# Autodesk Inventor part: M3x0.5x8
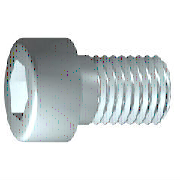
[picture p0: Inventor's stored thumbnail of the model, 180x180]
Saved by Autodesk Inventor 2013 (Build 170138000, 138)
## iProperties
IsCustomPart: 1
Company: 한국ATC센터
Created: 2009-02
Part Number: M3x0.5x8
Material: 강, 연강
Description: 6각머리 태핑 나사
Document SubType Name: Modeling
Standard: KS B 1003
Designer: KYOUNG IL JANG
Standards Organization: KS
Language: ko-KR
Size Designation: M 4 x 12
Categories: <MemberInstance><Categories><Category DisplayName="조임쇠" InternalName="e4da775c-781d-43d5-af7c-5136215cf5a6" Mnemonic="FSTN"><Category DisplayName="볼트" InternalN
Density: 7.86 g/cm^3
Mass: 1.37432 g
Surface Area: 2.58399 cm^2
Volume: 0.174849 cm^3
Vendor: CBT Solutions
Author: KYOUNG IL JANG
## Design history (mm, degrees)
sketch "스케치1"
  geometry: L1 (-0.867, 0)-(16, 0); L2 (16, 0)-(16, 1.5); L3 (16, 1.5)-(1.25, 1.5); L4 (1.25, 1.5)-(0.943, 1.5); L5 (0.943, 1.5)-(0, 1.5); L6 (0, 1.5)-(0, 2.75); L7 (0, 2.75)-(-3, 2.75); L8 (-3, 2.75)-(-3, 1.443); L9 (-3, 1.443)-(-1.7, 1.443); L10 (-1.7, 1.443)-(-0.867, 0); L11 (-6.8, 0)-(19.8, 0) reference; L12 (0, -0.55)-(0, 3.3) reference; L13 (1.25, 1.5)-(0, 1.5)
  constraints: 22 end point, 6 parallel, 2 collinear, 2 perpendicular, 1 horizontal, 1 point on line
  dimensions: "d1" = 14.75 distance from line of L3.end L2 (= GEL); "d2" = 0.30683 distance of L4.end L3.end (computed from GAL); "d3" = 3 distance between parallel lines of L8 L6 (= KOH); "d4" = 1.3 distance of L8.end L9.end (= INTI); "d5" = 60 deg angle of L10 L1; "d6" = 3 diameter of L3 L1 (= GD); "d7" = 3 diameter of L5 L1 (= BDM); "d8" = 2.88675 diameter of L9 L1 (= 1.1547 x SW); "d9" = 5.5 diameter of L7 L1 (= KOD); "d26" = 16 distance between parallel lines of L12 L2 (= NLG)
revolve "본체" sketch "스케치1" stored, may be unused: angle "d10" = 90 deg
sketch "스케치2"
  geometry: L1 (0, -3.85)-(0, 3.85) reference; L2 (-3.85, 0)-(3.85, 0) reference; L3 (1.443, 0)-(0.722, -1.25); L4 (0.722, -1.25)-(-0.722, -1.25); L5 (-0.722, -1.25)-(-1.443, 0); L6 (-1.443, 0)-(-0.722, 1.25); L7 (-0.722, 1.25)-(0.722, 1.25); L8 (0.722, 1.25)-(1.443, 0); 2 further points
  constraints: 12 end point, 1 coincident, 1 horizontal alignment, 1 point on line, 12 other
extrude "슬롯" join sketch "스케치2" stored distance "d11" = 10; taper "d12" = 0 deg
workplane "Work Plane1"
fillet "Fillet2" dims "d30" = 0.1 (= R)
body "Solid1"
fillet "모깎기1" dims "d17" = 0.3 (= RR)
feature "스레드" dims "d13" = 14.75 (= GEL), "d14" = 0
chamfer "모따기1" distance "d15" = 0.30673 (= -0.5 x SPD + 0.5 x GD); stored, may be unused: second distance "d16" = 0.30673 (= GUL), angle "d27" = 45 deg
other parameters: "GD" = 3 (= NND) [user parameter; used in 2 equation terms], "NLG" = 16 [user parameter; used in 1 equation term], "GEL" = 14.75 [user parameter; used in 2 equation terms], "KOD" = 5.5 [user parameter; used in 1 equation term], "KOH" = 3 [user parameter; used in 1 equation term], "INTI" = 1.3 [user parameter; used in 1 equation term], "GAL" = 0.30673 (= 0.61345 x PTC) [user parameter; used in 1 equation term], "GUL" = 0.30673 (= 0.61345 x PTC) [user parameter; used in 1 equation term], "BDM" = 3 (= NND) [user parameter; used in 1 equation term], "SW" = 2.5 [user parameter; used in 2 equation terms], "RR" = 0.3 [user parameter; used in 1 equation term], "SPD" = 2.38655 (= NND - 1.2269 x PTC) [user parameter; used in 1 equation term], "d19" = 0, "d28" = 0, "d29" = 0, "R" = 0.1 [user parameter; used in 1 equation term], "PHH" = 0.1 [user parameter], "GD1" = 2.38655 (= THREADDIA - 1.2269 x PTC) [user parameter], "THREADDIA" = 3 [user parameter; used in 1 equation term], "FAWI" = 45 deg [user parameter], "PTC" = 0.5 [user parameter; used in 5 equation terms], "NND" = 3 [user parameter; used in 3 equation terms], "TOA" = 30 deg [user parameter], "E0" = 2.8875 (= 1.155 x SW) [user parameter]
